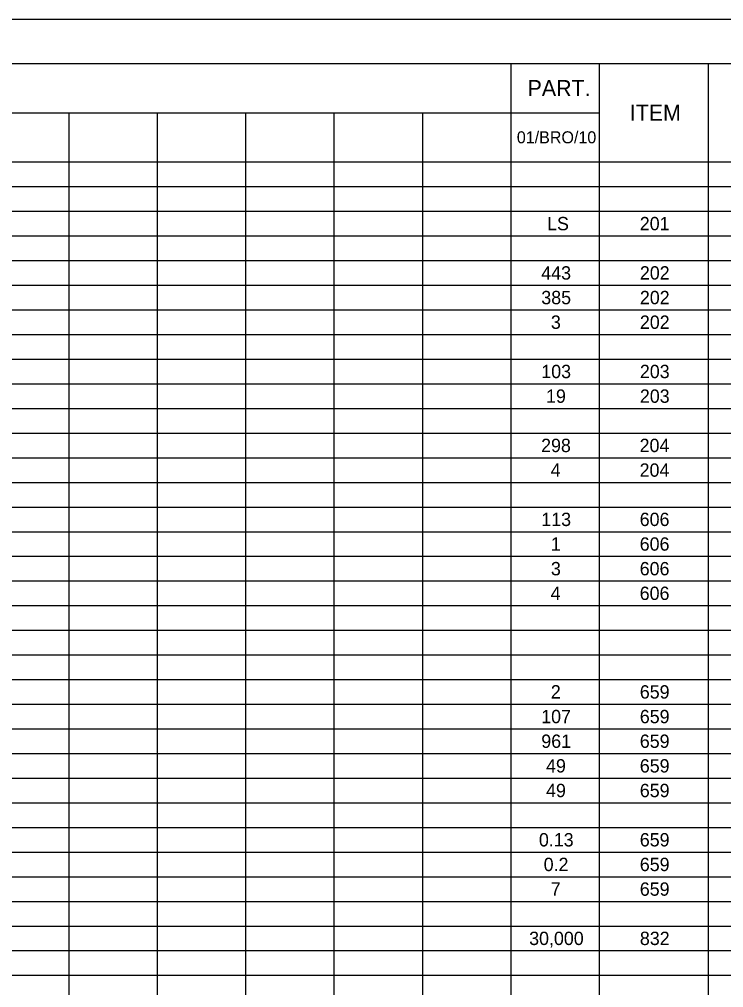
# Model space of a CAD drawing. Extents: x 0 to 34, y 0 to 22.
# Drawn here: x 8.98 to 16.98, y 11 to 22 of the extents above; entities that cross this region are included whole.
import ezdxf

# ---------------------------------------------------------------- set-up
doc = ezdxf.new("R2010")
doc.units = 0
for name, color, linetype in [('Default', 7, 'Continuous'), ('SH_Border', 7, 'Continuous'), ('SH_Cut_Line', 7, 'Continuous')]:
    doc.layers.add(name, color=color, linetype=linetype)

msp = doc.modelspace()

# ---------------------------------------------------------------- linework, layer by layer
at = {"layer": 'Default'}
for p, q in [((1.5, 21.5), (32, 21.5)), ((14.56, 21.5), (14.56, 0.5)), ((15.564, 21.5), (15.564, 0.5)), ((16.799, 21.5), (16.799, 0.5)), ((1.5, 20.94), (15.564, 20.94)), ((9.537, 20.94), (9.537, 0.5)), ((10.541, 20.94), (10.541, 0.5)), ((11.546, 20.94), (11.546, 0.5)), ((12.55, 20.94), (12.55, 0.5)), ((13.555, 20.94), (13.555, 0.5)), ((1.5, 20.38), (32, 20.38)), ((1.5, 20.1), (32, 20.1)), ((1.5, 19.82), (32, 19.82)), ((1.5, 19.54), (32, 19.54)), ((1.5, 19.26), (32, 19.26)), ((1.5, 18.98), (32, 18.98)), ((1.5, 18.7), (32, 18.7)), ((1.5, 18.42), (32, 18.42)), ((1.5, 18.14), (32, 18.14)), ((1.5, 17.86), (32, 17.86)), ((1.5, 17.58), (32, 17.58)), ((1.5, 17.3), (32, 17.3)), ((1.5, 17.02), (32, 17.02)), ((1.5, 16.74), (32, 16.74)), ((1.5, 16.46), (32, 16.46)), ((1.5, 16.18), (32, 16.18)), ((1.5, 15.9), (32, 15.9)), ((1.5, 15.62), (32, 15.62)), ((1.5, 15.34), (32, 15.34)), ((1.5, 15.06), (32, 15.06)), ((1.5, 14.78), (32, 14.78)), ((1.5, 14.5), (32, 14.5)), ((1.5, 14.22), (32, 14.22)), ((1.5, 13.94), (32, 13.94)), ((1.5, 13.66), (32, 13.66)), ((1.5, 13.38), (32, 13.38)), ((1.5, 13.1), (32, 13.1)), ((1.5, 12.82), (32, 12.82)), ((1.5, 12.54), (32, 12.54)), ((1.5, 12.26), (32, 12.26)), ((1.5, 11.98), (32, 11.98)), ((1.5, 11.7), (32, 11.7)), ((1.5, 11.42), (32, 11.42)), ((1.5, 11.14), (32, 11.14))]:
    msp.add_line(p, q, dxfattribs=at)
at = {"layer": 'SH_Border'}
msp.add_lwpolyline([(1.5, 21.5), (33.5, 21.5), (33.5, 0.5), (1.5, 0.5)], close=True, dxfattribs=at)
at = {"layer": 'SH_Cut_Line'}
msp.add_lwpolyline([(0, 0), (34, 0), (34, 22), (0, 22)], close=True, dxfattribs=at)

# ---------------------------------------------------------------- texts
at = {"layer": 'Default'}
for s, height, p in [('PART.', 0.1818, (14.749, 21.129)), ('ITEM', 0.1818, (15.91, 20.849)), ('01/BRO/10', 0.1364, (14.627, 20.592)), ('LS', 0.1515, (14.971, 19.604)), ('201', 0.1515, (16.024, 19.604)), ('443', 0.1515, (14.905, 19.044)), ('202', 0.1515, (16.025, 19.044)), ('385', 0.1515, (14.905, 18.764)), ('202', 0.1515, (16.025, 18.764)), ('3', 0.152, (15.014, 18.484)), ('202', 0.1515, (16.025, 18.484)), ('103', 0.1515, (14.905, 17.924)), ('203', 0.1515, (16.025, 17.924)), ('19', 0.1515, (14.959, 17.644)), ('203', 0.1515, (16.025, 17.644)), ('298', 0.1515, (14.903, 17.084)), ('204', 0.1515, (16.022, 17.084)), ('4', 0.152, (15.011, 16.804)), ('204', 0.1515, (16.022, 16.804)), ('113', 0.1515, (14.905, 16.244)), ('606', 0.1515, (16.023, 16.244)), ('1', 0.152, (15.013, 15.964)), ('606', 0.1515, (16.023, 15.964)), ('3', 0.152, (15.014, 15.684)), ('606', 0.1515, (16.023, 15.684)), ('4', 0.152, (15.011, 15.404)), ('606', 0.1515, (16.023, 15.404)), ('2', 0.152, (15.013, 14.284)), ('659', 0.1515, (16.024, 14.284)), ('107', 0.1515, (14.904, 14.004)), ('659', 0.1515, (16.024, 14.004)), ('961', 0.1515, (14.905, 13.724)), ('659', 0.1515, (16.024, 13.724)), ('49', 0.1515, (14.959, 13.444)), ('659', 0.1515, (16.024, 13.444)), ('49', 0.1515, (14.959, 13.164)), ('659', 0.1515, (16.024, 13.164)), ('0.13', 0.1515, (14.878, 12.604)), ('659', 0.1515, (16.024, 12.604)), ('0.2', 0.1515, (14.932, 12.324)), ('659', 0.1515, (16.024, 12.324)), ('7', 0.152, (15.012, 12.044)), ('659', 0.1515, (16.024, 12.044)), ('30,000', 0.1515, (14.767, 11.484)), ('832', 0.1515, (16.025, 11.484))]:
    msp.add_text(s, height=height, dxfattribs=at).set_placement(p)

doc.saveas('drawing.dxf')
